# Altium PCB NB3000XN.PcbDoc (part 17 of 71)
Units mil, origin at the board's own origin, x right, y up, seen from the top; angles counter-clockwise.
Board outline 9527.56 x 6929.77 mil, 6 copper layers (Top Layer, GND+SHIELD, MidLayer1, MidLayer2, P2 - 3V3+5V0, Bottom Layer), stack 62.375 mil thick; 832 components, 1027 nets, 4655 pads, 4981 vias.
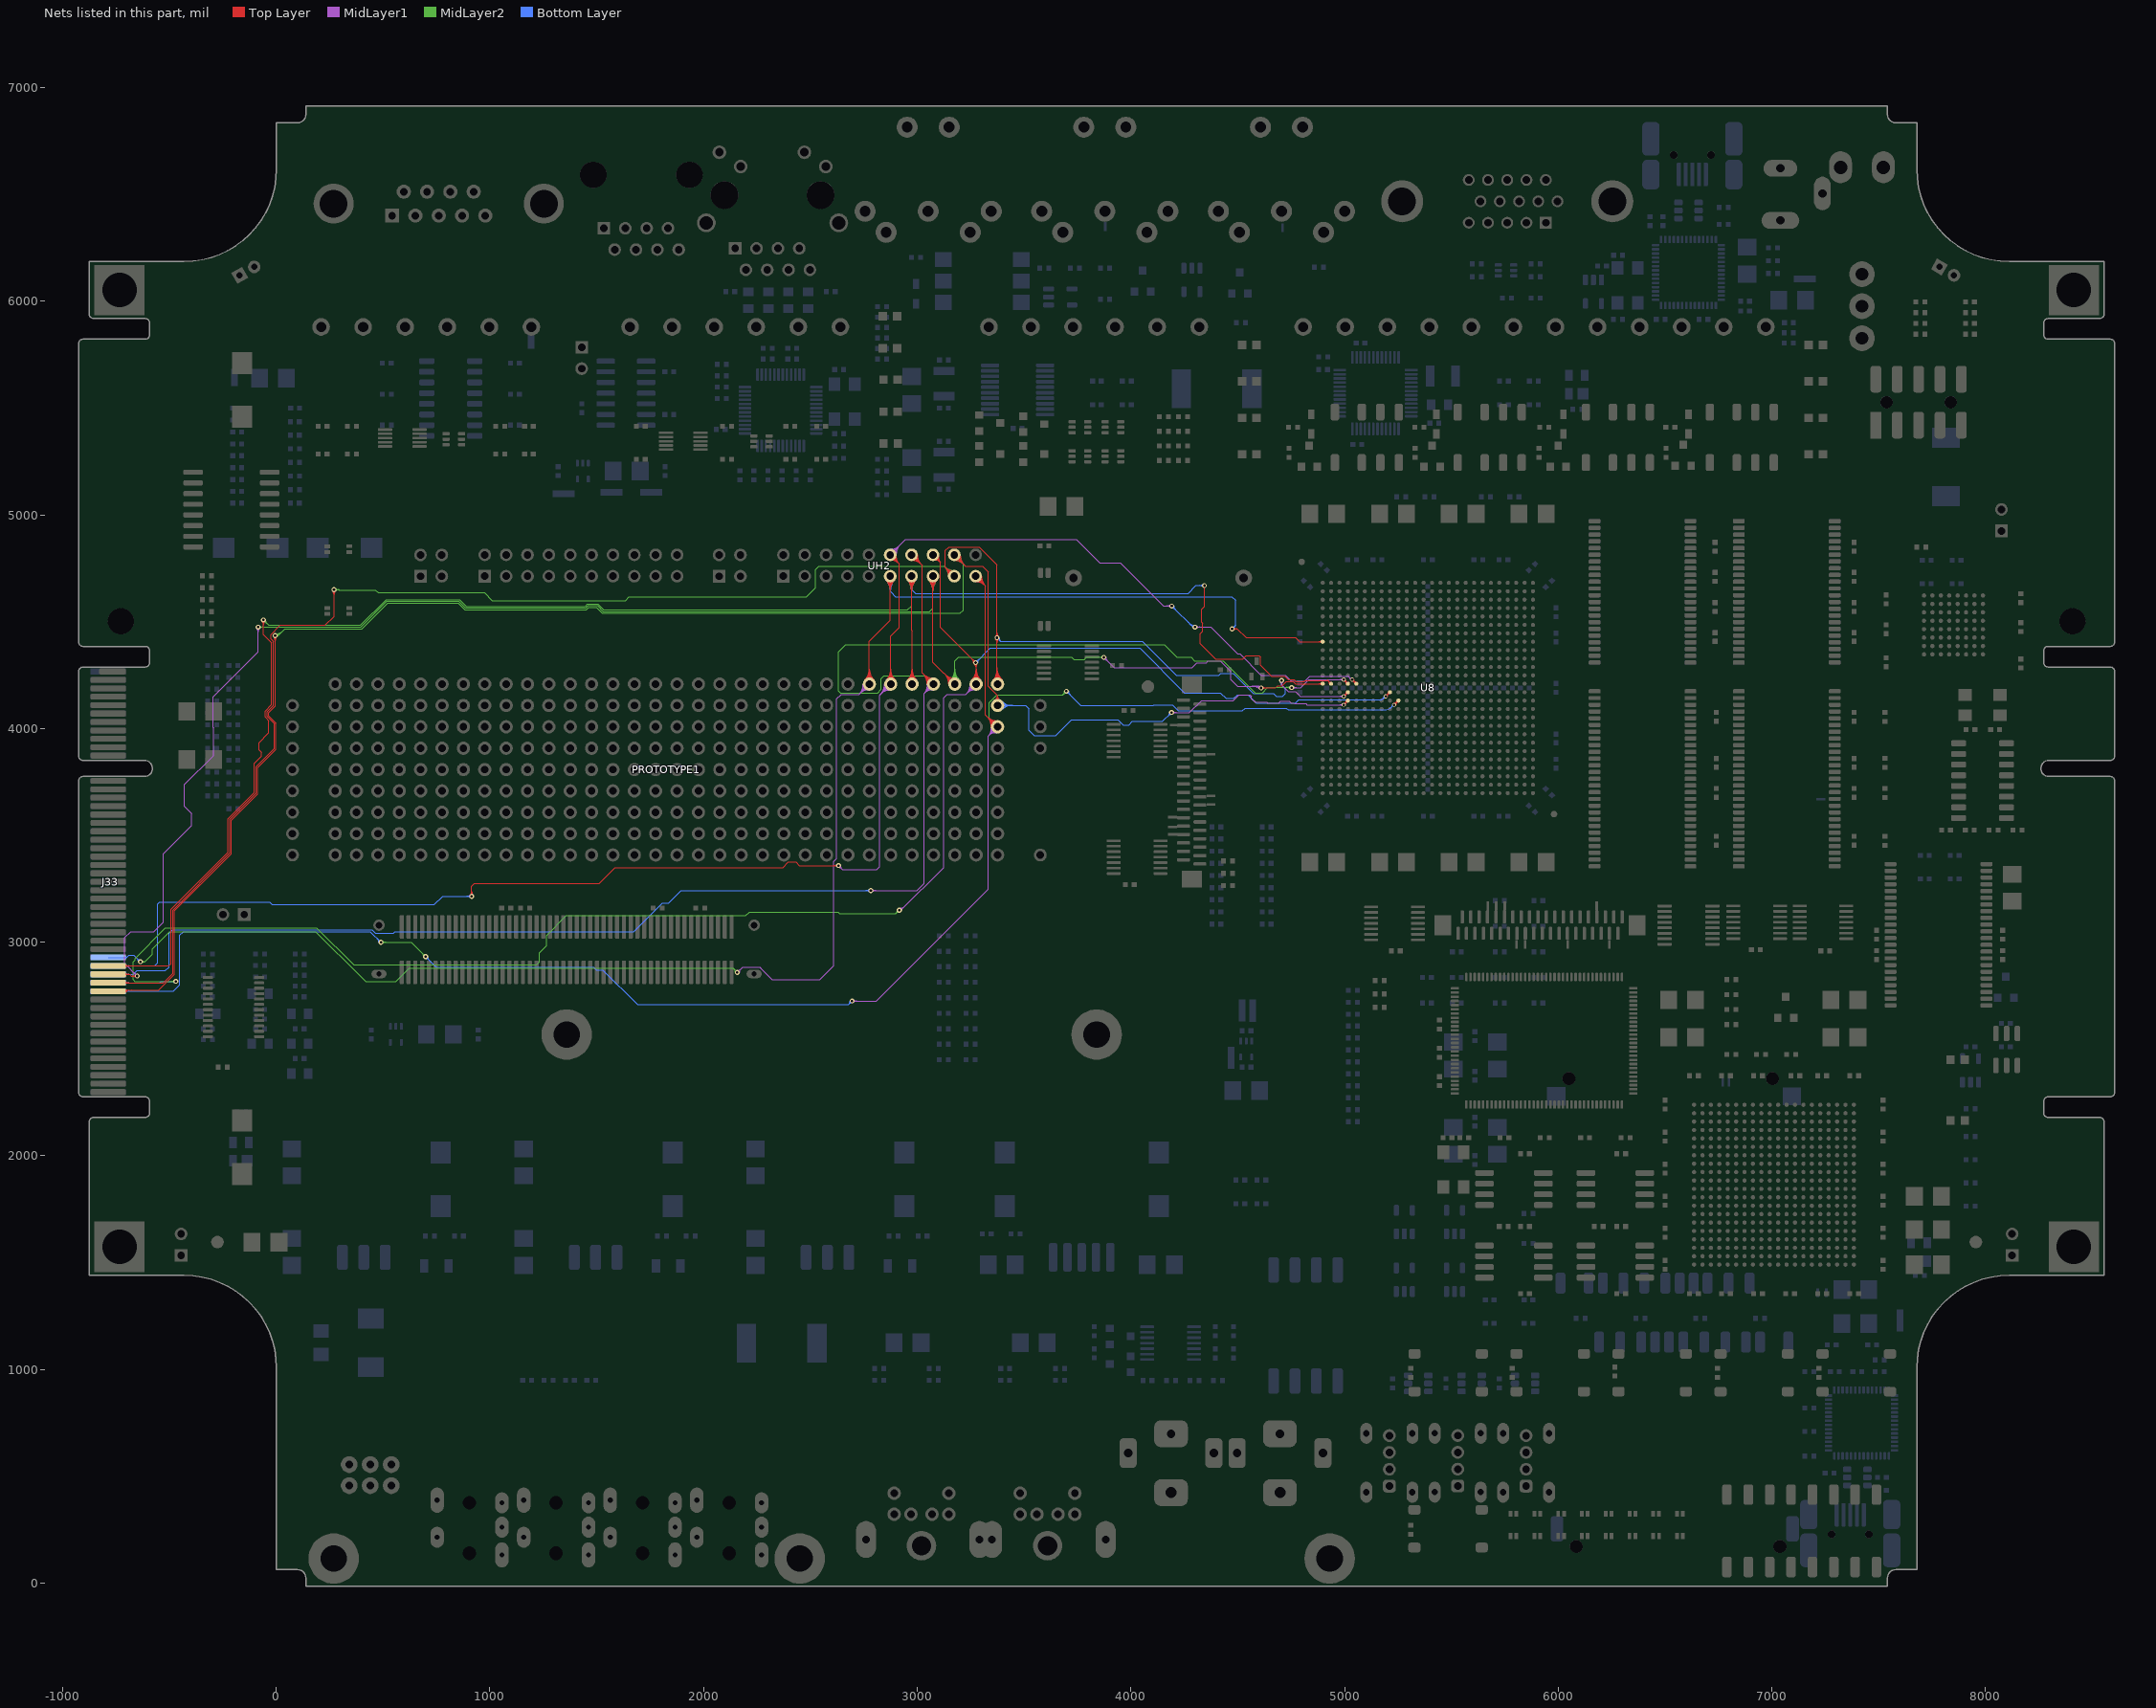
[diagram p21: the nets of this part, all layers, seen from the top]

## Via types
v1: diameter 23, hole 11.81, Top Layer to Bottom Layer, 3672 vias
v2: diameter 26, hole 11.81, Top Layer to Bottom Layer, 461 vias
v3: diameter 19, hole 11.81, Top Layer to Bottom Layer, tented both sides, 396 vias
v4: diameter 23.62, hole 11.81, Top Layer to Bottom Layer, 288 vias
v5: diameter 20, hole 11.81, Top Layer to Bottom Layer, 91 vias
v6: diameter 23, hole 11.81, Top Layer to Bottom Layer, tented both sides, 50 vias
v7: diameter 31, hole 11.81, Top Layer to Bottom Layer, 15 vias
v8: diameter 27.56, hole 11.81, Top Layer to Bottom Layer, tented both sides, 4 vias
v9: diameter 29, hole 11.81, Top Layer to Bottom Layer, 3 vias
v10: diameter 21, hole 11.81, Top Layer to Bottom Layer, 1 vias

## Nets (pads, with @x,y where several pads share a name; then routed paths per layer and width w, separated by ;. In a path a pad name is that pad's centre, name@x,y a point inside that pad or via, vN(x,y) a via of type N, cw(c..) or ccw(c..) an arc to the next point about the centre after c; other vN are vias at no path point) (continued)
ATE.UIO.IO27: J33.B33 PROTOTYPE1.H26 U8.H1 UH2.11 | length 9772.1
  Top Layer w4: PROTOTYPE1.H26@2755.62,4228.74 ccw(c2706.11,4278.25) 2776.12,4278.25 ccw(c2846.13,4278.25) PROTOTYPE1.H26@2796.63,4228.74 ; PROTOTYPE1.H26@2758.44,4225.91 ccw(c2715.77,4268.59) 2776.12,4268.59 ccw(c2836.48,4268.59) PROTOTYPE1.H26@2793.8,4225.91 ; PROTOTYPE1.H26@2761.27,4223.08 ccw(c2725.42,4258.93) 2776.12,4258.93 ccw(c2826.82,4258.93) PROTOTYPE1.H26@2790.97,4223.08 ; PROTOTYPE1.H26@2764.1,4220.26 ccw(c2735.08,4249.28) 2776.12,4249.28 ccw(c2817.16,4249.28) PROTOTYPE1.H26@2788.14,4220.26 ; PROTOTYPE1.H26@2766.93,4217.43 ccw(c2744.74,4239.62) 2776.12,4239.62 ccw(c2807.51,4239.62) PROTOTYPE1.H26@2785.31,4217.43 ; PROTOTYPE1.H26@2776.12,4208.23 2776.12,4408.37 2873.76,4506.01 UH2.11@2873.76,4713.23 ; UH2.11@2854.29,4693.77 cw(c2807.3,4646.78) 2873.76,4646.78 cw(c2940.21,4646.78) UH2.11@2893.22,4693.77 ; UH2.11@2857.12,4696.6 cw(c2816.96,4656.43) 2873.76,4656.43 cw(c2930.56,4656.43) UH2.11@2890.4,4696.6 ; UH2.11@2859.95,4699.43 cw(c2826.61,4666.09) 2873.76,4666.09 cw(c2920.9,4666.09) UH2.11@2887.57,4699.43 ; UH2.11@2862.78,4702.25 cw(c2836.27,4675.75) 2873.76,4675.75 cw(c2911.24,4675.75) UH2.11@2884.74,4702.25 ; v1(4473.52,4466.71) 4498.29,4466.71 4539.13,4425.87 4770.7,4425.87 4790.03,4406.54 4860,4406.54 4870,4406.54 U8.H1@4897.87,4406.54 ; v1@4477.41,4462.82 cw(c4486.8,4453.43) 4486.8,4466.71 cw(c4486.8,4479.99) v1@4477.41,4470.6 ; v1@4480.24,4459.99 cw(c4496.46,4443.77) 4496.46,4466.71 cw(c4496.46,4489.64) v1@4480.24,4473.43 ; U8.H1@4892.57,4401.23 ccw(c4879.77,4388.43) 4879.77,4406.54 ccw(c4879.77,4424.64) U8.H1@4892.57,4411.84 ; U8.H1@4892.68,4401.34 ccw(c4880.15,4388.81) 4880.15,4406.54 ccw(c4880.15,4424.26) U8.H1@4892.68,4411.73
  MidLayer1 w4: v1(2157.86,2858.37) 2182.86,2883.37 2263.86,2883.37 2266.12,2881.12 ; v1@2157.86,2863.87 ccw(c2157.86,2877.15) 2167.25,2867.76 ccw(c2176.64,2858.37) v1@2163.36,2858.37 ; v1@2157.86,2867.87 ccw(c2157.86,2890.81) 2174.07,2874.59 ccw(c2190.29,2858.37) v1@2167.36,2858.37 ; 2265,2880 2320.29,2824.71 2545.21,2824.71 2610,2889.5 2610,3378.18 2623.52,3391.71 2623.52,4138.52 2645,4160 2727.89,4160 ; PROTOTYPE1.H26@2747.13,4207.7 cw(c2681.42,4206.47) 2727.89,4160 ; PROTOTYPE1.H26@2751.13,4207.77 cw(c2694.48,4206.72) 2734.54,4166.66 cw(c2774.6,4126.59) PROTOTYPE1.H26@2775.66,4183.24 ; PROTOTYPE1.H26@2755.12,4207.84 cw(c2707.54,4206.96) 2741.19,4173.31 cw(c2774.85,4139.66) PROTOTYPE1.H26@2775.73,4187.24 ; PROTOTYPE1.H26@2759.12,4207.92 cw(c2720.61,4207.2) 2747.85,4179.96 cw(c2775.09,4152.72) PROTOTYPE1.H26@2775.8,4191.24 ; PROTOTYPE1.H26@2775.58,4179.24 ccw(c2774.36,4113.53) 2727.89,4160 ; PROTOTYPE1.H26@2776.12,4208.23 2727.89,4160
  MidLayer2 w4: v1(-635.48,2908.37) -615,2908.37 ; v1@-631.28,2904.82 cw(c-623.62,2898.35) -623.62,2908.37 cw(c-623.62,2918.4) v1@-631.28,2911.93 ; v1@-628.22,2902.24 cw(c-615,2891.06) -615,2908.37 ; v1@-628.22,2914.51 ccw(c-615,2925.69) -615,2908.37 ; v1@2148.36,2858.37 ccw(c2125.42,2858.37) 2141.64,2874.59 ccw(c2157.86,2890.81) v1@2157.86,2867.87 ; v1@2152.36,2858.37 ccw(c2139.08,2858.37) 2148.47,2867.76 ccw(c2157.86,2877.15) v1@2157.86,2863.87 ; v1(2157.86,2858.37) 2138.23,2878 623,2878 560,2815 418.69,2815 395.84,2837.85 183.65,3050.04 -498.5,3050.04 -580,2968.54 -580,2943.37 -615,2908.37
  Bottom Layer w4: J33.B33@-785.98,2928.45 -701.3,2928.45 ; J33.B33@-705.79,2925.1 cw(c-701.31,2923.77) -701.31,2928.45 ; J33.B33@-705.79,2931.8 ccw(c-701.31,2933.13) -701.31,2928.45 ; v1@-644.98,2908.37 ccw(c-667.91,2908.37) -651.69,2924.59 ccw(c-635.48,2940.81) v1@-635.48,2917.87 ; v1@-640.98,2908.37 ccw(c-654.25,2908.37) -644.86,2917.76 ccw(c-635.48,2927.15) v1@-635.48,2913.87 ; v1(-635.48,2908.37) -667.45,2940.35 -689.41,2940.35 -701.3,2928.45 ; UH2.11@2854.29,4693.77 cw(c2804.3,4643.78) 2875,4643.78 ; UH2.11@2857.12,4696.6 cw(c2813.96,4653.44) 2875,4653.44 ; UH2.11@2859.95,4699.43 cw(c2823.62,4663.09) 2875,4663.09 ; UH2.11@2862.78,4702.25 cw(c2833.28,4672.75) 2875,4672.75 ; UH2.11@2865.61,4705.08 cw(c2842.93,4682.41) 2875,4682.41 ; UH2.11@2873.76,4713.23 UH2.11@2875,4713.23 ; 2875,4649.77 cw(c2937.22,4649.77) UH2.11@2893.22,4693.77 ; 2875,4659.43 cw(c2927.56,4659.43) UH2.11@2890.4,4696.6 ; 2875,4669.09 cw(c2917.91,4669.09) UH2.11@2887.57,4699.43 ; 2875,4678.74 cw(c2908.25,4678.74) UH2.11@2884.74,4702.25 ; UH2.11@2875,4715 UH2.11@2875,4713.23 ; v1(4473.52,4466.71) 4490.19,4483.37 4490.19,4600.04 4473.52,4616.71 2898.52,4616.71 2875,4640.23 UH2.11@2875,4713.23 ; v1@4473.52,4472.21 ccw(c4473.52,4485.49) 4482.91,4476.1 ccw(c4492.3,4466.71) v1@4479.02,4466.71 ; v1@4473.52,4476.21 ccw(c4473.52,4499.14) 4489.74,4482.93 ccw(c4505.96,4466.71) v1@4483.02,4466.71
ATE.UIO.IO28: J33.B34 PROTOTYPE1.H27 U8.N5 UH2.12 | length 10153.7
  Top Layer w4: v1@908.3,3221.74 ccw(c892.14,3238.01) 915.07,3237.93 ccw(c938.01,3237.86) v1@921.74,3221.7 ; v1@911.12,3218.9 ccw(c901.76,3228.32) 915.04,3228.28 ccw(c928.32,3228.24) v1@918.9,3218.88 ; v1(915,3215) 915.15,3262.19 928,3275.04 1512.21,3275.04 1586.88,3349.71 2371.52,3349.71 2396.86,3375.04 2431.86,3375.04 2448.52,3358.37 v1(2631.86,3358.37) ; v1@2625.14,3351.66 ccw(c2608.92,3335.44) 2608.92,3358.37 ccw(c2608.92,3381.31) v1@2625.14,3365.09 ; v1@2627.97,3354.49 ccw(c2618.58,3345.1) 2618.58,3358.37 ccw(c2618.58,3371.65) v1@2627.97,3362.26 ; PROTOTYPE1.H27@2855.62,4228.74 ccw(c2806.11,4278.25) 2876.12,4278.25 ccw(c2946.13,4278.25) PROTOTYPE1.H27@2896.63,4228.74 ; PROTOTYPE1.H27@2858.44,4225.91 ccw(c2815.77,4268.59) 2876.12,4268.59 ccw(c2936.48,4268.59) PROTOTYPE1.H27@2893.8,4225.91 ; PROTOTYPE1.H27@2861.27,4223.08 ccw(c2825.42,4258.93) 2876.12,4258.93 ccw(c2926.82,4258.93) PROTOTYPE1.H27@2890.97,4223.08 ; PROTOTYPE1.H27@2864.1,4220.26 ccw(c2835.08,4249.28) 2876.12,4249.28 ccw(c2917.16,4249.28) PROTOTYPE1.H27@2888.14,4220.26 ; PROTOTYPE1.H27@2866.93,4217.43 ccw(c2844.74,4239.62) 2876.12,4239.62 ccw(c2907.51,4239.62) PROTOTYPE1.H27@2885.31,4217.43 ; UH2.12@2873.76,4813.23 2915.19,4771.8 ; UH2.12@2875.2,4797.77 cw(c2877.75,4770.48) 2897.13,4789.86 cw(c2916.51,4809.24) UH2.12@2889.22,4811.79 ; UH2.12@2875.57,4793.79 cw(c2878.77,4759.47) 2903.15,4783.84 cw(c2927.52,4808.22) UH2.12@2893.2,4811.42 ; UH2.12@2875.94,4789.81 cw(c2879.8,4748.46) 2909.17,4777.82 cw(c2938.53,4807.19) UH2.12@2897.18,4811.05 ; PROTOTYPE1.H27@2876.12,4208.23 2876.12,4433.37 2915.19,4472.44 2915.19,4771.8 ; UH2.12@2876.32,4785.83 cw(c2880.83,4737.45) 2915.19,4771.8 ; UH2.12@2901.17,4810.68 ccw(c2949.55,4806.16) 2915.19,4771.8 ; v3(5035.67,4229.37) U8.N5@5055.35,4209.69 ; U8.N5@5047.85,4209.69 ccw(c5029.75,4209.69) 5042.55,4222.49 ccw(c5055.35,4235.29) U8.N5@5055.35,4217.19 ; U8.N5@5048.01,4209.69 ccw(c5030.29,4209.69) 5042.82,4222.22 ccw(c5055.35,4234.75) U8.N5@5055.35,4217.03 ; 5048.47,4216.57 ccw(c5035.67,4203.76) 5035.67,4221.87 cw(c5035.67,4203.76) 5048.47,4216.57 ; 5048.47,4216.57 cw(c5061.28,4229.37) 5043.17,4229.37 ccw(c5061.28,4229.37) 5048.47,4216.57
  MidLayer1 w4: v1@2631.86,3348.87 cw(c2631.86,3325.94) 2648.07,3342.16 cw(c2664.29,3358.37) v1@2641.36,3358.37 ; v1@2631.86,3352.87 cw(c2631.86,3339.6) 2641.25,3348.99 cw(c2650.64,3358.37) v1@2637.36,3358.37 ; v1(2631.86,3358.37) 2650.23,3340 2810,3340 2823.52,3353.52 2823.52,4155.64 PROTOTYPE1.H27@2876.12,4208.23 ; PROTOTYPE1.H27@2847.12,4208.23 cw(c2777.11,4208.23) 2826.62,4158.73 cw(c2876.12,4109.22) PROTOTYPE1.H27@2876.12,4179.23 ; PROTOTYPE1.H27@2851.12,4208.23 cw(c2790.77,4208.23) 2833.44,4165.56 cw(c2876.12,4122.88) PROTOTYPE1.H27@2876.12,4183.23 ; PROTOTYPE1.H27@2855.12,4208.23 cw(c2804.42,4208.23) 2840.27,4172.39 cw(c2876.12,4136.54) PROTOTYPE1.H27@2876.12,4187.23 ; PROTOTYPE1.H27@2859.12,4208.23 cw(c2818.08,4208.23) 2847.1,4179.21 cw(c2876.12,4150.19) PROTOTYPE1.H27@2876.12,4191.23 ; PROTOTYPE1.H27@2863.12,4208.23 cw(c2831.74,4208.23) 2853.93,4186.04 cw(c2876.12,4163.85) PROTOTYPE1.H27@2876.12,4195.23 ; UH2.12@2873.52,4813.23 UH2.12@2873.76,4813.23 2945.54,4885 3744.71,4885 3855,4774.71 3951.61,4774.71 4152.61,4573.71 v1(4191.52,4573.71) ; UH2.12@2873.76,4828.76 ccw(c2873.76,4866.28) 2900.29,4839.75 ; UH2.12@2873.76,4832.76 ccw(c2873.76,4879.93) 2907.11,4846.58 ; UH2.12@2873.76,4836.76 ccw(c2873.76,4893.59) 2913.94,4853.41 ; UH2.12@2873.76,4840.76 ccw(c2873.76,4907.25) 2920.77,4860.23 ; UH2.12@2889.29,4813.23 cw(c2926.74,4813.23) 2900.26,4839.72 ; UH2.12@2893.29,4813.23 cw(c2940.4,4813.23) 2907.09,4846.55 ; UH2.12@2897.29,4813.23 cw(c2954.06,4813.23) 2913.91,4853.38 ; UH2.12@2901.29,4813.23 cw(c2967.71,4813.23) 2920.74,4860.21 ; v1@4184.81,4566.99 ccw(c4168.59,4550.77) 4168.59,4573.71 ccw(c4168.59,4596.64) v1@4184.81,4580.43 ; v1@4187.64,4569.82 ccw(c4178.25,4560.43) 4178.25,4573.71 ccw(c4178.25,4586.99) v1@4187.64,4577.6 ; v1@4303.89,4471.11 cw(c4313.38,4461.62) 4313.38,4475.04 ; v1@4303.89,4478.89 ccw(c4313.18,4488.18) 4313.18,4475.04 ; v1@4306.72,4468.28 cw(c4323.03,4451.97) 4323.03,4475.04 ; v1@4306.72,4481.72 ccw(c4322.84,4497.84) 4322.84,4475.04 ; 5022.09,4240.76 ccw(c5012.16,4230.83) 5012.16,4244.88 4918.62,4244.88 4870,4244.88 4860,4244.88 4837.69,4244.88 4815.19,4222.37 4751.19,4222.37 4723.52,4250.04 4609.84,4250.04 4509.84,4350.04 4498.52,4350.04 4373.52,4475.04 v1@4300.04,4475.04 ; v3@5028.2,4228.72 ccw(c5010.16,4227.14) 5021.8,4241.01 ccw(c5033.44,4254.88) v3@5035.02,4236.84 ; v1(4300,4475) v1@4300.04,4475.04
  Bottom Layer w4: J33.B34@-785.98,2889.08 -567.81,2889.08 -554.41,2902.48 -554.41,3179.28 -546.69,3187 -29.82,3187 -19,3176.19 740.09,3176.19 778.9,3215 v1(915,3215) ; J33.B34@-711.58,2883.58 cw(c-698.3,2870.3) -698.3,2889.08 ; J33.B34@-711.58,2894.58 ccw(c-698.3,2907.86) -698.3,2889.08 ; J33.B34@-708.76,2880.75 cw(c-688.65,2860.64) -688.65,2889.08 cw(c-688.64,2917.52) J33.B34@-708.76,2897.41 ; v1@908.28,3208.28 ccw(c892.06,3192.06) 892.06,3215 ccw(c892.06,3237.93) v1@908.28,3221.72 ; v1@911.11,3211.11 ccw(c901.72,3201.72) 901.72,3215 ccw(c901.72,3228.28) v1@911.11,3218.89 ; v1@4191.52,4564.21 cw(c4191.52,4541.27) 4207.74,4557.49 cw(c4223.96,4573.71) v1@4201.02,4573.71 ; v1@4191.52,4568.21 cw(c4191.52,4554.93) 4200.91,4564.32 cw(c4210.3,4573.71) v1@4197.02,4573.71 ; v1(4191.52,4573.71) 4290.19,4475.04 4306.86,4475.04 4306.82,4475 v1(4300,4475) ; 4267.11,4498.13 ccw(c4300,4531.02) v1@4300,4484.5 ; 4273.93,4491.3 ccw(c4300,4517.36) v1@4300,4480.5 ; 4280.76,4484.47 ccw(c4300,4503.71) v1@4300,4476.5 ; 4287.59,4477.64 ccw(c4300,4490.05) v1@4300,4472.5
ATE.UIO.IO29: J33.A34 PROTOTYPE1.H28 U8.N2 UH2.13 | length 9997.1
  Top Layer w4: J33.A34@-785.98,2889.08 -503.06,2889.08 -492.14,2900 -492.14,3154.02 -292.32,3353.85 -225.35,3420.81 -225.35,3578.34 -102,3701.69 -102,3838.1 -68.14,3871.96 -68.14,3888.14 -81,3901 -81,3933.85 -35,3979.85 -35,4037.56 -51.48,4054.04 -51.48,4081.15 -21,4111.63 -21,4401 -59.81,4439.81 v1(-59.81,4508.37) ; J33.A34@-711.58,2883.58 cw(c-698.3,2870.3) -698.3,2889.08 ; J33.A34@-711.58,2894.58 ccw(c-698.3,2907.86) -698.3,2889.08 ; J33.A34@-708.76,2880.75 cw(c-688.65,2860.64) -688.65,2889.08 cw(c-688.64,2917.52) J33.A34@-708.76,2897.41 ; v1@-66.53,4501.66 cw(c-82.74,4485.44) -59.81,4485.44 cw(c-36.87,4485.44) v1@-53.09,4501.66 ; v1@-63.7,4504.49 cw(c-73.09,4495.1) -59.81,4495.1 cw(c-46.53,4495.1) v1@-55.92,4504.49 ; UH2.13@2954.29,4693.77 cw(c2907.3,4646.78) 2973.76,4646.78 cw(c3040.21,4646.78) UH2.13@2993.22,4693.77 ; PROTOTYPE1.H28@2955.62,4228.74 ccw(c2906.11,4278.25) 2976.12,4278.25 ccw(c3046.13,4278.25) PROTOTYPE1.H28@2996.63,4228.74 ; UH2.13@2957.12,4696.6 cw(c2916.96,4656.43) 2973.76,4656.43 cw(c3030.56,4656.43) UH2.13@2990.4,4696.6 ; PROTOTYPE1.H28@2958.44,4225.91 ccw(c2915.77,4268.59) 2976.12,4268.59 ccw(c3036.48,4268.59) PROTOTYPE1.H28@2993.8,4225.91 ; UH2.13@2959.95,4699.43 cw(c2926.61,4666.09) 2973.76,4666.09 cw(c3020.9,4666.09) UH2.13@2987.57,4699.43 ; PROTOTYPE1.H28@2961.27,4223.08 ccw(c2925.42,4258.93) 2976.12,4258.93 ccw(c3026.82,4258.93) PROTOTYPE1.H28@2990.97,4223.08 ; UH2.13@2962.78,4702.25 cw(c2936.27,4675.75) 2973.76,4675.75 cw(c3011.24,4675.75) UH2.13@2984.74,4702.25 ; PROTOTYPE1.H28@2964.1,4220.26 ccw(c2935.08,4249.28) 2976.12,4249.28 ccw(c3017.16,4249.28) PROTOTYPE1.H28@2988.14,4220.26 ; PROTOTYPE1.H28@2966.93,4217.43 ccw(c2944.74,4239.62) 2976.12,4239.62 ccw(c3007.51,4239.62) PROTOTYPE1.H28@2985.31,4217.43 ; UH2.13@2973.76,4713.23 2973.76,4460.74 2976.12,4458.37 PROTOTYPE1.H28@2976.12,4208.23 ; v1(4344.52,4669.37) 4344.52,4570.84 4332,4558.31 4332,4497.27 4335,4494.27 4335,4454.52 4331.86,4451.37 ; U8.N2@4929.9,4209.69 ccw(c4912.17,4209.69) 4924.71,4222.22 ; U8.N2@4937.24,4217.03 cw(c4937.24,4234.75) 4924.71,4222.22 ; 4324.02,4443.54 4331.86,4451.37 ; 4324.02,4443.54 4331.86,4451.37 ; 4324.02,4443.54 4324.02,4397.81 4396.8,4325.04 4523.52,4325.04 4540.19,4341.71 4600.52,4341.71 4606.86,4335.37 4606.86,4296.71 4658.52,4245.04 4720.21,4245.04 4736.54,4228.71 4746,4228.71 4762.92,4228.71 4771.63,4220 4786.9,4220 4801,4220 4810,4220 4815.19,4225.19 4855.26,4225.19 4860,4225.19 4870,4225.19 4917.53,4225.19 cw(c4917.53,4215.04) 4924.71,4222.22
  MidLayer2 w4: v1@-59.81,4498.87 cw(c-59.81,4475.94) -43.59,4492.16 cw(c-27.37,4508.37) v1@-50.31,4508.37 ; v1@-59.81,4502.87 cw(c-59.81,4489.6) -50.42,4498.99 cw(c-41.03,4508.37) v1@-54.31,4508.37 ; v1(-59.81,4508.37) -34.81,4483.37 394.96,4483.37 515.4,4603.81 858,4603.81 889.31,4572.5 1445.98,4572.5 1448.52,4575.04 1456.86,4583.37 1505.5,4583.37 1532.88,4556 2955,4556 2973.76,4574.76 UH2.13@2973.76,4713.23 ; UH2.13@2954.29,4693.77 cw(c2907.3,4646.78) 2973.76,4646.78 cw(c3040.22,4646.78) UH2.13@2993.22,4693.77 ; UH2.13@2957.12,4696.6 cw(c2916.96,4656.43) 2973.76,4656.43 cw(c3030.56,4656.43) UH2.13@2990.4,4696.6 ; UH2.13@2959.95,4699.43 cw(c2926.62,4666.09) 2973.76,4666.09 cw(c3020.9,4666.09) UH2.13@2987.57,4699.43 ; UH2.13@2962.78,4702.25 cw(c2936.27,4675.75) 2973.76,4675.75 cw(c3011.25,4675.75) UH2.13@2984.74,4702.25
  Bottom Layer w4: UH2.13@2955.3,4692.81 cw(c2917.73,4651.24) 2973.76,4651.24 ; UH2.13@2957.98,4695.78 cw(c2925.87,4660.25) 2973.76,4660.25 cw(c3021.65,4660.25) UH2.13@2989.54,4695.78 ; UH2.13@2960.66,4698.75 cw(c2934.01,4669.26) 2973.76,4669.26 cw(c3013.51,4669.26) UH2.13@2986.85,4698.75 ; UH2.13@2963.35,4701.72 cw(c2942.15,4678.27) 2973.76,4678.27 cw(c3005.37,4678.27) UH2.13@2984.17,4701.72 ; UH2.13@2973.76,4713.23 2973.76,4651.24 ; UH2.13@2992.22,4692.81 ccw(c3029.79,4651.24) 2973.76,4651.24 ; v1@4337.81,4662.66 ccw(c4321.59,4646.44) 4321.59,4669.37 ccw(c4321.59,4692.31) v1@4337.81,4676.09 ; v1@4340.64,4665.49 ccw(c4331.25,4656.1) 4331.25,4669.37 ccw(c4331.25,4682.65) v1@4340.64,4673.26 ; v1(4344.52,4669.37) 4304.37,4669.37 4267.71,4632.71 2992.29,4632.71 2973.76,4651.24
ATE.UIO.IO30: J33.B35 PROTOTYPE1.H29 U8.N4 UH2.14 | length 10675.6
  Top Layer w4: UH2.14@2973.76,4785.71 cw(c2973.76,4719.25) 3020.75,4766.24 cw(c3067.74,4813.23) UH2.14@3001.29,4813.23 ; UH2.14@2973.76,4789.71 cw(c2973.76,4732.91) 3013.92,4773.07 cw(c3054.09,4813.23) UH2.14@2997.29,4813.23 ; UH2.14@2973.76,4793.71 cw(c2973.76,4746.56) 3007.09,4779.9 cw(c3040.43,4813.23) UH2.14@2993.29,4813.23 ; UH2.14@2973.76,4797.71 cw(c2973.76,4760.22) 3000.27,4786.73 cw(c3026.77,4813.23) UH2.14@2989.29,4813.23 ; UH2.14@2973.76,4813.23 3023.52,4763.47 3023.52,4260.83 PROTOTYPE1.H29@3076.12,4208.23 ; PROTOTYPE1.H29@3047.12,4208.23 ccw(c2977.11,4208.23) 3026.62,4257.74 ccw(c3076.12,4307.25) PROTOTYPE1.H29@3076.12,4237.23 ; PROTOTYPE1.H29@3051.12,4208.23 ccw(c2990.77,4208.23) 3033.44,4250.91 ccw(c3076.12,4293.59) PROTOTYPE1.H29@3076.12,4233.23 ; PROTOTYPE1.H29@3055.12,4208.23 ccw(c3004.42,4208.23) 3040.27,4244.08 ccw(c3076.12,4279.93) PROTOTYPE1.H29@3076.12,4229.23 ; PROTOTYPE1.H29@3059.12,4208.23 ccw(c3018.08,4208.23) 3047.1,4237.26 ccw(c3076.12,4266.28) PROTOTYPE1.H29@3076.12,4225.23 ; PROTOTYPE1.H29@3063.12,4208.23 ccw(c3031.74,4208.23) 3053.93,4230.43 ccw(c3076.12,4252.62) PROTOTYPE1.H29@3076.12,4221.23 ; v3(4996.3,4229.37) U8.N4@5015.98,4209.69 ; U8.N4@5008.48,4209.69 ccw(c4990.38,4209.69) 5003.18,4222.49 ccw(c5015.98,4235.29) U8.N4@5015.98,4217.19 ; U8.N4@5008.64,4209.69 ccw(c4990.92,4209.69) 5003.45,4222.22 ccw(c5015.98,4234.75) U8.N4@5015.98,4217.03 ; 5009.1,4216.57 cw(c5021.91,4229.37) 5003.8,4229.37 ccw(c5021.91,4229.37) 5009.1,4216.57 ; 5009.1,4216.57 ccw(c4996.3,4203.76) 4996.3,4221.87 cw(c4996.3,4203.76) 5009.1,4216.57
  MidLayer1 w4: v1(2782.86,3241.71) 2998.52,3241.71 3031.86,3275.04 3031.86,4163.97 ; v1@2786.75,3237.82 cw(c2796.14,3228.43) 2796.14,3241.71 cw(c2796.14,3254.99) v1@2786.75,3245.6 ; v1@2789.57,3234.99 cw(c2805.79,3218.77) 2805.79,3241.71 cw(c2805.79,3264.64) v1@2789.57,3248.43 ; PROTOTYPE1.H29@3047.22,4205.85 cw(c2994.34,4201.49) 3031.86,4163.97 ; PROTOTYPE1.H29@3051.21,4206.18 cw(c3005.62,4202.42) 3037.96,4170.08 cw(c3070.31,4137.74) PROTOTYPE1.H29@3074.07,4183.32 ; PROTOTYPE1.H29@3055.19,4206.51 cw(c3016.9,4203.35) 3044.07,4176.18 cw(c3071.24,4149.02) PROTOTYPE1.H29@3074.39,4187.31 ; PROTOTYPE1.H29@3059.18,4206.84 cw(c3028.18,4204.28) 3050.17,4182.29 cw(c3072.17,4160.3) PROTOTYPE1.H29@3074.72,4191.29 ; PROTOTYPE1.H29@3073.74,4179.33 ccw(c3069.37,4126.46) 3031.86,4163.97 ; PROTOTYPE1.H29@3076.12,4208.23 3031.86,4163.97 ; v1(4752.52,4191.71) 4795.84,4191.71 4833.5,4229.37 4855.26,4229.37 4860,4229.37 4870,4229.37 4918.62,4229.37 v3(4996.3,4229.37) ; v1@4756.41,4187.82 cw(c4765.8,4178.43) 4765.8,4191.71 cw(c4765.8,4204.99) v1@4756.41,4195.6 ; v1@4759.24,4184.99 cw(c4775.46,4168.77) 4775.46,4191.71 cw(c4775.46,4214.64) v1@4759.24,4198.43 ; v3@4991.11,4224.18 ccw(c4978.57,4211.64) 4978.57,4229.37 ccw(c4978.57,4247.1) v3@4991.11,4234.56 ; 4978.19,4229.37 cw(c4978.19,4211.26) 4991,4224.07 ccw(c4978.19,4211.26) 4978.19,4229.37 ; 4978.19,4229.37 ccw(c4978.19,4247.48) 4991,4234.67 cw(c4978.19,4247.48) 4978.19,4229.37
  MidLayer2 w4: PROTOTYPE1.H29@3047.62,4213.59 ccw(c3010.68,4220.52) 3037.26,4247.1 ; PROTOTYPE1.H29@3051.55,4212.85 ccw(c3019.7,4218.83) 3042.62,4241.74 ccw(c3065.53,4264.65) PROTOTYPE1.H29@3071.51,4232.81 ; PROTOTYPE1.H29@3055.48,4212.11 ccw(c3028.73,4217.13) 3047.98,4236.38 ccw(c3067.22,4255.63) PROTOTYPE1.H29@3072.25,4228.87 ; PROTOTYPE1.H29@3059.41,4211.37 ccw(c3037.76,4215.44) 3053.34,4231.02 ccw(c3068.92,4246.6) PROTOTYPE1.H29@3072.98,4224.94 ; PROTOTYPE1.H29@3070.77,4236.74 cw(c3063.83,4273.68) 3037.26,4247.1 ; PROTOTYPE1.H29@3076.12,4208.23 3037.25,4247.1 ; 4727.17,4192.71 cw(c4727.17,4166.36) v1@4745.81,4184.99 ; 4732,4192.71 ccw(c4732,4212.23) v1@4745.81,4198.43 ; 4736.83,4192.71 cw(c4736.83,4176.02) v1@4748.64,4187.82 ; v1(4752.52,4191.71) 4751.52,4192.71 4641.19,4192.71 4615.19,4166.71 4581.86,4166.71 4432.52,4316.04 4298.86,4316.04 4281.52,4333.37 4215.19,4333.37 4156.86,4391.71 2665.19,4391.71 2631.86,4358.37 2631.86,4175.04 2640.19,4166.71 2815.19,4166.71 2831.86,4183.37 2831.86,4233.37 2845.59,4247.1 3037.25,4247.1
  Bottom Layer w4: J33.B35@-785.98,2849.71 -668.14,2849.71 -651.14,2866.71 -518.14,2866.71 -501.48,2883.37 -501.48,3041.71 -484.81,3058.37 448.33,3058.37 465,3041.71 550,3041.71 556.6,3048.31 1672.48,3048.31 1807.21,3183.04 1836.88,3183.04 1895.54,3241.71 v1(2782.86,3241.71) ; J33.B35@-711.58,2844.21 cw(c-698.3,2830.93) -698.3,2849.71 ; J33.B35@-711.58,2855.21 ccw(c-698.3,2868.49) -698.3,2849.71 ; J33.B35@-708.76,2841.38 cw(c-688.65,2821.27) -688.65,2849.71 cw(c-688.64,2878.15) J33.B35@-708.76,2858.04 ; v1@2776.14,3234.99 ccw(c2759.92,3218.77) 2759.92,3241.71 ccw(c2759.92,3264.64) v1@2776.14,3248.43 ; v1@2778.97,3237.82 ccw(c2769.58,3228.43) 2769.58,3241.71 ccw(c2769.58,3254.99) v1@2778.97,3245.6
ATE.UIO.IO31: J33.A35 PROTOTYPE1.H30 U8.N1 UH2.15 | length 10161.6
  Top Layer w4: J33.A35@-785.98,2849.71 -685,2849.71 -677,2841.71 v1(-650.48,2841.71) ; J33.A35@-711.58,2844.21 cw(c-698.3,2830.93) -698.3,2849.71 ; J33.A35@-711.58,2855.21 ccw(c-698.3,2868.49) -698.3,2849.71 ; J33.A35@-708.76,2841.38 cw(c-688.65,2821.27) -688.65,2849.71 cw(c-688.64,2878.15) J33.A35@-708.76,2858.04 ; v1@-657.19,2834.99 ccw(c-673.41,2818.77) -673.41,2841.71 ccw(c-673.41,2864.64) v1@-657.19,2848.43 ; v1@-654.36,2837.82 ccw(c-663.75,2828.43) -663.75,2841.71 ccw(c-663.75,2854.99) v1@-654.36,2845.6 ; UH2.15@3054.29,4693.77 cw(c3007.3,4646.78) 3073.76,4646.78 cw(c3140.21,4646.78) UH2.15@3093.22,4693.77 ; UH2.15@3057.12,4696.6 cw(c3016.96,4656.43) 3073.76,4656.43 cw(c3130.56,4656.43) UH2.15@3090.4,4696.6 ; UH2.15@3059.95,4699.43 cw(c3026.61,4666.09) 3073.76,4666.09 cw(c3120.9,4666.09) UH2.15@3087.57,4699.43 ; UH2.15@3062.78,4702.25 cw(c3036.27,4675.75) 3073.76,4675.75 cw(c3111.24,4675.75) UH2.15@3084.74,4702.25 ; UH2.15@3073.76,4713.23 3073.76,4310.6 PROTOTYPE1.H30@3176.12,4208.23 ; PROTOTYPE1.H30@3147.12,4208.23 ccw(c3077.11,4208.23) 3126.62,4257.74 ccw(c3176.12,4307.25) PROTOTYPE1.H30@3176.12,4237.23 ; PROTOTYPE1.H30@3151.12,4208.23 ccw(c3090.77,4208.23) 3133.44,4250.91 ccw(c3176.12,4293.59) PROTOTYPE1.H30@3176.12,4233.23 ; PROTOTYPE1.H30@3155.12,4208.23 ccw(c3104.42,4208.23) 3140.27,4244.08 ccw(c3176.12,4279.93) PROTOTYPE1.H30@3176.12,4229.23 ; PROTOTYPE1.H30@3159.12,4208.23 ccw(c3118.08,4208.23) 3147.1,4237.26 ccw(c3176.12,4266.28) PROTOTYPE1.H30@3176.12,4225.23 ; PROTOTYPE1.H30@3163.12,4208.23 ccw(c3131.74,4208.23) 3153.93,4230.43 ccw(c3176.12,4252.62) PROTOTYPE1.H30@3176.12,4221.23 ; v1(4610,4190) 4677.17,4190 4687.88,4200.71 4707.52,4200.71 4727.52,4220.71 4759.61,4220.71 4770.63,4209.69 4813,4209.69 ; v1@4613.89,4186.11 cw(c4623.28,4176.72) 4623.28,4190 cw(c4623.28,4203.28) v1@4613.89,4193.89 ; v1@4616.72,4183.28 cw(c4632.93,4167.06) 4632.93,4190 cw(c4632.93,4212.93) v1@4616.72,4196.72 ; 4811.31,4209.69 4813,4209.69 ; 4855.26,4209.68 4856.86,4209.68 ; U8.N1@4892.57,4204.38 ccw(c4879.77,4191.58) 4879.77,4209.69 ccw(c4879.77,4227.79) U8.N1@4892.57,4214.99 ; U8.N1@4892.68,4204.49 ccw(c4880.15,4191.96) 4880.15,4209.69 ccw(c4880.15,4227.41) U8.N1@4892.68,4214.88 ; U8.N1@4897.87,4209.69 4870,4209.69 4860,4209.69 4825,4209.69 4813,4209.69
  MidLayer1 w4: v1@-659.98,2841.71 ccw(c-682.91,2841.71) -666.69,2857.93 ccw(c-650.48,2874.14) v1@-650.48,2851.21 ; v1@-655.98,2841.71 ccw(c-669.25,2841.71) -659.86,2851.1 ccw(c-650.48,2860.49) v1@-650.48,2847.21 ; v1(-650.48,2841.71) -709.81,2901.04 -709.81,3021.46 -681.22,3050.04 -572.33,3050.04 -529,3093.37 -529,3201.2 ; -528.98,3201.22 -528.98,3412.99 -395,3546.97 -395,3602.38 -428.81,3636.19 -428.81,3737.82 -293.23,3873.4 -293.23,4003.46 -295,4005.23 -295,4148.18 -84.81,4358.37 v1(-84.81,4475.04) ; v1@-91.53,4468.32 cw(c-107.74,4452.11) -84.81,4452.11 cw(c-61.87,4452.11) v1@-78.09,4468.32 ; v1@-88.7,4471.15 cw(c-98.09,4461.76) -84.81,4461.76 cw(c-71.53,4461.76) v1@-80.92,4471.15 ; v1@3873.52,4323.87 cw(c3873.52,4300.94) 3889.74,4317.16 cw(c3905.96,4333.37) v1@3883.02,4333.37 ; v1@3873.52,4327.87 cw(c3873.52,4314.6) 3882.91,4323.99 cw(c3892.3,4333.37) v1@3879.02,4333.37 ; v1(3873.52,4333.37) 3921.9,4285 4286.79,4285 4310,4308.21 4353.21,4308.21 4361.54,4316.54 4419.66,4316.54 4468.86,4267.35 4468.86,4229.71 4499.86,4198.71 4601.29,4198.71 v1(4610,4190) ; 4566.04,4198.71 cw(c4566.04,4146.04) v1@4603.28,4183.28 ; 4575.7,4198.71 cw(c4575.7,4155.7) v1@4606.11,4186.11 ; 4585.36,4198.71 cw(c4585.36,4165.36) v1@4608.94,4188.94 ; 4595.01,4198.71 cw(c4595.01,4175.01) v1@4611.77,4191.77
  MidLayer2 w4: v1(-84.81,4475.04) 397.94,4475.04 518.71,4595.81 854.19,4595.81 885.5,4564.5 1449.3,4564.5 1460.17,4575.37 1502.19,4575.37 1529.56,4548 3058,4548 3073.76,4563.76 UH2.15@3073.76,4713.23 ; v1@-80.92,4471.15 cw(c-71.53,4461.76) -71.53,4475.04 cw(c-71.53,4488.32) v1@-80.92,4478.93 ; v1@-78.09,4468.32 cw(c-61.87,4452.11) -61.87,4475.04 cw(c-61.87,4497.98) v1@-78.09,4481.76 ; UH2.15@3054.29,4693.77 cw(c3007.3,4646.78) 3073.76,4646.78 cw(c3140.22,4646.78) UH2.15@3093.22,4693.77 ; UH2.15@3057.12,4696.6 cw(c3016.96,4656.43) 3073.76,4656.43 cw(c3130.56,4656.43) UH2.15@3090.4,4696.6 ; UH2.15@3059.95,4699.43 cw(c3026.62,4666.09) 3073.76,4666.09 cw(c3120.9,4666.09) UH2.15@3087.57,4699.43 ; UH2.15@3062.78,4702.25 cw(c3036.27,4675.75) 3073.76,4675.75 cw(c3111.25,4675.75) UH2.15@3084.74,4702.25 ; PROTOTYPE1.H30@3155.62,4228.74 ccw(c3106.1,4278.25) 3176.12,4278.25 ; PROTOTYPE1.H30@3158.44,4225.91 ccw(c3115.76,4268.6) 3176.12,4268.6 ccw(c3236.47,4268.58) PROTOTYPE1.H30@3193.8,4225.91 ; PROTOTYPE1.H30@3161.27,4223.08 ccw(c3125.42,4258.94) 3176.12,4258.94 ccw(c3226.81,4258.93) PROTOTYPE1.H30@3190.97,4223.08 ; PROTOTYPE1.H30@3164.1,4220.26 ccw(c3135.07,4249.28) 3176.12,4249.28 ccw(c3217.16,4249.27) PROTOTYPE1.H30@3188.14,4220.26 ; PROTOTYPE1.H30@3166.93,4217.43 ccw(c3144.73,4239.63) 3176.12,4239.63 ccw(c3207.5,4239.61) PROTOTYPE1.H30@3185.31,4217.43 ; PROTOTYPE1.H30@3176.12,4208.23 3176.12,4316.31 3193.19,4333.37 3723.52,4333.37 3734.19,4322.71 3781.86,4322.71 3792.52,4333.37 v1(3873.52,4333.37) ; 3176.12,4278.24 ccw(c3246.13,4278.24) PROTOTYPE1.H30@3196.63,4228.74 ; v1@3866.81,4326.66 ccw(c3850.59,4310.44) 3850.59,4333.37 ccw(c3850.59,4356.31) v1@3866.81,4340.09 ; v1@3869.64,4329.49 ccw(c3860.25,4320.1) 3860.25,4333.37 ccw(c3860.25,4346.65) v1@3869.64,4337.26
ATE.UIO.IO32: J33.B36 PROTOTYPE1.H31 U8.P9 UH2.16 | length 10071.3
  Top Layer w4: UH2.16@3073.76,4813.23 3109.4,4777.59 ; UH2.16@3077.91,4794.15 cw(c3082.8,4771.7) 3099.04,4787.95 cw(c3115.29,4804.2) UH2.16@3092.84,4809.08 ; UH2.16@3078.76,4790.24 cw(c3084.65,4763.19) 3104.22,4782.77 cw(c3123.8,4802.34) UH2.16@3096.75,4808.23 ; UH2.16@3079.61,4786.34 cw(c3086.5,4754.69) 3109.4,4777.59 ; UH2.16@3100.66,4807.38 ccw(c3132.31,4800.49) 3109.4,4777.59 ; PROTOTYPE1.H31@3255.62,4228.74 ccw(c3206.11,4278.25) 3276.12,4278.25 ccw(c3346.13,4278.25) PROTOTYPE1.H31@3296.63,4228.74 ; PROTOTYPE1.H31@3258.44,4225.91 ccw(c3215.77,4268.59) 3276.12,4268.59 ccw(c3336.48,4268.59) PROTOTYPE1.H31@3293.8,4225.91 ; PROTOTYPE1.H31@3261.27,4223.08 ccw(c3225.42,4258.93) 3276.12,4258.93 ccw(c3326.82,4258.93) PROTOTYPE1.H31@3290.97,4223.08 ; v1@3264.02,4308.37 ccw(c3241.09,4308.37) 3257.31,4324.59 ccw(c3273.52,4340.81) v1@3273.52,4317.87 ; PROTOTYPE1.H31@3264.1,4220.26 ccw(c3235.08,4249.28) 3276.12,4249.28 ccw(c3317.16,4249.28) PROTOTYPE1.H31@3288.14,4220.26 ; v1@3266.81,4301.66 cw(c3244.32,4279.17) 3276.12,4279.17 ; PROTOTYPE1.H31@3266.93,4217.43 ccw(c3244.74,4239.62) 3276.12,4239.62 ccw(c3307.51,4239.62) PROTOTYPE1.H31@3285.31,4217.43 ; v1@3268.02,4308.37 ccw(c3254.75,4308.37) 3264.14,4317.76 ccw(c3273.52,4327.15) v1@3273.52,4313.87 ; v1@3269.64,4304.49 cw(c3253.98,4288.83) 3276.12,4288.83 ; PROTOTYPE1.H31@3276.12,4208.23 3276.12,4305.78 v1(3273.52,4308.37) 3109.4,4472.49 3109.4,4777.59 ; 3276.12,4291.71 cw(c3290.19,4291.71) v1@3280.24,4301.66 ; v3(5193.15,4150.63) U8.P9@5212.83,4170.31 ; U8.P9@5205.33,4170.31 cw(c5187.23,4170.31) 5200.03,4157.51 cw(c5212.83,4144.71) U8.P9@5212.83,4162.81 ; U8.P9@5205.49,4170.31 cw(c5187.77,4170.31) 5200.3,4157.78 cw(c5212.83,4145.25) U8.P9@5212.83,4162.97 ; 5205.95,4163.43 cw(c5193.15,4176.24) 5193.15,4158.13 ccw(c5193.15,4176.24) 5205.95,4163.43 ; 5205.95,4163.43 ccw(c5218.76,4150.63) 5200.65,4150.63 cw(c5218.76,4150.63) 5205.95,4163.43
  MidLayer1 w4: v1(2916.19,3150.04) 2923.52,3150.04 3123.52,3350.04 3123.52,4143.52 3140,4160 3227.89,4160 ; v1@2916.19,3151.54 ccw(c2916.19,3172.87) 2931.27,3157.79 ; v1@2916.19,3155.54 ccw(c2916.19,3186.52) 2938.1,3164.62 ; v1@2916.19,3159.54 ccw(c2916.19,3200.18) 2944.93,3171.44 ; v1@2925.69,3150.04 cw(c2930.92,3150.04) 2927.22,3153.74 ; PROTOTYPE1.H31@3247.13,4207.7 cw(c3181.42,4206.47) 3227.89,4160 ; PROTOTYPE1.H31@3251.13,4207.77 cw(c3194.48,4206.72) 3234.54,4166.66 cw(c3274.6,4126.59) PROTOTYPE1.H31@3275.66,4183.24 ; PROTOTYPE1.H31@3255.12,4207.84 cw(c3207.54,4206.96) 3241.19,4173.31 cw(c3274.85,4139.66) PROTOTYPE1.H31@3275.73,4187.24 ; PROTOTYPE1.H31@3259.12,4207.92 cw(c3220.61,4207.2) 3247.85,4179.96 cw(c3275.09,4152.72) PROTOTYPE1.H31@3275.8,4191.24 ; PROTOTYPE1.H31@3275.58,4179.24 ccw(c3274.36,4113.53) 3227.89,4160 ; PROTOTYPE1.H31@3276.12,4208.23 3227.89,4160
  MidLayer2 w4: v1@-476.53,2809.99 ccw(c-492.74,2793.77) -492.74,2816.71 ccw(c-492.74,2839.64) v1@-476.53,2823.43 ; v1@-473.7,2812.82 ccw(c-483.09,2803.43) -483.09,2816.71 ccw(c-483.09,2829.99) v1@-473.7,2820.6 ; v1(-469.81,2816.71) -661.71,2816.71 -670,2825 -670,2907.38 -661.14,2916.24 -661.14,2924.37 -518.81,3066.71 189.61,3066.71 362.31,2894 1219,2894 1231.86,2906.86 1231.86,2950.37 1265.19,2983.71 1265.19,3032.04 1358.19,3125.04 2197.92,3125.04 2214.25,3141.37 2628.63,3141.37 2636.96,3133.04 2899.19,3133.04 v1(2916.19,3150.04) ; v1@2906.69,3150.04 cw(c2883.76,3150.04) 2899.97,3133.82 cw(c2916.19,3117.61) v1@2916.19,3140.54 ; v1@2910.69,3150.04 cw(c2897.41,3150.04) 2906.8,3140.65 cw(c2916.19,3131.26) v1@2916.19,3144.54
  Bottom Layer w4: J33.B36@-785.98,2810.34 -545,2810.34 -538.63,2816.71 v1(-469.81,2816.71) ; J33.B36@-711.58,2804.84 cw(c-698.3,2791.56) -698.3,2810.34 cw(c-698.3,2829.12) J33.B36@-711.58,2815.84 ; J33.B36@-708.76,2802.01 cw(c-688.65,2781.9) -688.65,2810.34 cw(c-688.64,2838.78) J33.B36@-708.76,2818.67 ; v1@-476.53,2809.99 ccw(c-492.74,2793.77) -492.74,2816.71 ccw(c-492.74,2839.64) v1@-476.53,2823.43 ; v1@-473.7,2812.82 ccw(c-483.09,2803.43) -483.09,2816.71 ccw(c-483.09,2829.99) v1@-473.7,2820.6 ; v1(3273.52,4308.37) 3341.19,4376.04 3361.04,4376.04 4041.6,4376.04 4250.93,4166.71 4419.65,4166.71 4444.65,4141.71 4481.86,4141.71 4498.52,4158.37 4548.52,4158.37 4586.9,4120 4770.15,4120 4785.27,4135.12 4855.26,4135.12 4860,4135.12 4870,4135.12 5076.1,4135.12 5169.64,4135.12 ccw(c5169.64,4149.17) 5179.57,4139.24 ; v1@3273.52,4313.87 ccw(c3273.52,4327.15) 3282.91,4317.76 ccw(c3292.3,4308.37) v1@3279.02,4308.37 ; v1@3273.52,4317.87 ccw(c3273.52,4340.81) 3289.74,4324.59 ccw(c3305.96,4308.37) v1@3283.02,4308.37 ; v3@5185.68,4151.28 cw(c5167.64,4152.86) 5179.28,4138.99 cw(c5190.92,4125.12) v3@5192.5,4143.16
ATE.UIO.IO33: J33.A36 PROTOTYPE1.H32 U8.P4 UH2.17 | length 10171.6
  Top Layer w4: J33.A36@-785.98,2810.34 -527.49,2810.34 -484.14,2853.69 -484.14,3150.71 -235.05,3399.8 -217.35,3417.5 -217.35,3575.02 -100.05,3692.32 -94,3698.37 -94,3821.31 -9.14,3906.17 -9.14,4023.02 -43.14,4057.02 -43.14,4078.17 -13,4108.31 -13,4408 -25,4420 -25,4439.75 18.63,4483.37 228.86,4483.37 270.52,4525.04 v1(270.52,4650.04) ; J33.A36@-711.58,2804.84 cw(c-698.3,2791.56) -698.3,2810.34 cw(c-698.3,2829.12) J33.A36@-711.58,2815.84 ; J33.A36@-708.76,2802.01 cw(c-688.65,2781.9) -688.65,2810.34 cw(c-688.64,2838.78) J33.A36@-708.76,2818.67 ; v1@263.81,4643.32 cw(c247.59,4627.11) 270.52,4627.11 cw(c293.46,4627.11) v1@277.24,4643.32 ; v1@266.64,4646.15 cw(c257.25,4636.76) 270.52,4636.76 cw(c283.8,4636.76) v1@274.41,4646.15 ; UH2.17@3146.33,4715.55 ccw(c3096.5,4719.77) 3131.86,4755.13 ; UH2.17@3150.31,4715.22 ccw(c3107.72,4718.82) 3137.95,4749.04 ccw(c3168.17,4779.27) UH2.17@3171.77,4736.68 ; UH2.17@3154.3,4714.88 ccw(c3118.95,4717.87) 3144.04,4742.96 ccw(c3169.12,4768.04) UH2.17@3172.11,4732.69 ; UH2.17@3158.29,4714.54 ccw(c3130.18,4716.92) 3150.12,4736.87 ccw(c3170.07,4756.81) UH2.17@3172.45,4728.71 ; UH2.17@3171.44,4740.66 cw(c3167.22,4790.5) 3131.86,4755.13 ; UH2.17@3173.76,4713.23 3131.86,4755.13 ; PROTOTYPE1.H32@3355.62,4228.74 ccw(c3312.38,4271.98) 3373.52,4271.98 ; PROTOTYPE1.H32@3358.44,4225.91 ccw(c3322.04,4262.32) 3373.52,4262.32 ; PROTOTYPE1.H32@3361.27,4223.08 ccw(c3331.69,4252.66) 3373.52,4252.66 ; PROTOTYPE1.H32@3364.1,4220.26 ccw(c3341.35,4243.01) 3373.52,4243.01 ; v1@3366.81,4418.32 cw(c3350.59,4402.11) 3373.52,4402.11 cw(c3396.46,4402.11) v1@3380.24,4418.32 ; v1@3366.81,4431.76 ccw(c3350.59,4447.98) 3373.52,4447.98 ccw(c3396.46,4447.98) v1@3380.24,4431.76 ; v1@3369.64,4421.15 cw(c3360.25,4411.76) 3373.52,4411.76 cw(c3386.8,4411.76) v1@3377.41,4421.15 ; v1@3369.64,4428.93 ccw(c3360.25,4438.32) 3373.52,4438.32 ccw(c3386.8,4438.32) v1@3377.41,4428.93 ; 3373.52,4245.89 ccw(c3413.78,4245.89) PROTOTYPE1.H32@3385.31,4217.43 ; 3373.52,4255.55 ccw(c3423.43,4255.55) PROTOTYPE1.H32@3388.14,4220.26 ; 3373.52,4265.2 ccw(c3433.09,4265.2) PROTOTYPE1.H32@3390.97,4223.08 ; 3373.52,4274.86 ccw(c3442.75,4274.86) PROTOTYPE1.H32@3393.8,4225.91 ; 3373.52,4284.52 ccw(c3452.4,4284.52) PROTOTYPE1.H32@3396.63,4228.74 ; PROTOTYPE1.H32@3376.12,4208.23 3373.52,4210.83 v1(3373.52,4425.04) 3373.52,4766.71 3290.19,4850.04 3148.52,4850.04 3131.86,4833.37 3131.86,4755.13 ; v3(4996.3,4150.63) U8.P4@5015.98,4170.31 ; U8.P4@5008.48,4170.31 cw(c4990.38,4170.31) 5003.18,4157.51 cw(c5015.98,4144.71) U8.P4@5015.98,4162.81 ; U8.P4@5008.64,4170.31 cw(c4990.92,4170.31) 5003.45,4157.78 cw(c5015.98,4145.25) U8.P4@5015.98,4162.97 ; 5009.1,4163.43 cw(c4996.3,4176.24) 4996.3,4158.13 ccw(c4996.3,4176.24) 5009.1,4163.43 ; 5009.1,4163.43 ccw(c5021.91,4150.63) 5003.8,4150.63 cw(c5021.91,4150.63) 5009.1,4163.43
  MidLayer1 w4: v1@4699.34,4217.83 cw(c4687.8,4204.38) 4705.52,4204.38 ; v1@4701.94,4220.87 cw(c4695.26,4213.08) 4705.52,4213.08 cw(c4715.79,4213.08) v1@4709.11,4220.87 ; v1(4705.52,4225.04) 4705.52,4204.37 ; v1@4711.71,4217.83 ccw(c4723.25,4204.38) 4705.52,4204.38 ; v3@4991.11,4145.44 ccw(c4978.57,4132.9) 4978.57,4150.63 ccw(c4978.57,4168.36) v3@4991.11,4155.82 ; v3(4996.3,4150.63) 4918.62,4150.63 4870,4150.63 4860,4150.63 4793.87,4150.63 4770.79,4173.71 4736.19,4173.71 4705.52,4204.37 ; 4978.19,4150.63 cw(c4978.19,4132.52) 4991,4145.33 ccw(c4978.19,4132.52) 4978.19,4150.63 ; 4978.19,4150.63 ccw(c4978.19,4168.74) 4991,4155.93 cw(c4978.19,4168.74) 4978.19,4150.63
  MidLayer2 w4: v1(270.52,4650.04) 293.96,4650.04 295,4649 463.25,4649 476.44,4635.81 974.07,4635.81 1010.17,4599.71 1634.71,4599.71 1651.71,4616.71 2481.86,4616.71 2523.52,4658.37 2523.52,4743.52 2540,4760 3126.99,4760 UH2.17@3173.76,4713.23 ; v1@274.41,4646.15 cw(c283.8,4636.76) 283.8,4650.04 cw(c283.8,4663.32) v1@274.41,4653.93 ; v1@277.24,4643.32 cw(c293.46,4627.11) 293.46,4650.04 cw(c293.46,4672.98) v1@277.24,4656.76 ; UH2.17@3146.23,4713.33 ccw(c3080.56,4713.56) 3127,4760 ccw(c3173.44,4806.44) UH2.17@3173.66,4740.76 ; UH2.17@3150.23,4713.32 ccw(c3094.1,4713.51) 3133.79,4753.2 ccw(c3173.48,4792.9) UH2.17@3173.68,4736.76 ; UH2.17@3154.23,4713.3 ccw(c3107.64,4713.46) 3140.59,4746.41 ccw(c3173.53,4779.35) UH2.17@3173.69,4732.76 ; UH2.17@3158.23,4713.29 ccw(c3121.19,4713.42) 3147.38,4739.61 ccw(c3173.58,4765.81) UH2.17@3173.71,4728.76
  Bottom Layer w4: v1@3373.52,4415.54 cw(c3373.52,4392.61) 3389.74,4408.82 cw(c3405.96,4425.04) v1@3383.02,4425.04 ; v1@3373.52,4419.54 cw(c3373.52,4406.26) 3382.91,4415.65 cw(c3392.3,4425.04) v1@3379.02,4425.04 ; v1(3373.52,4425.04) 3390.52,4408.04 4054.86,4408.04 4083.58,4379.32 4212.86,4250.04 4412.21,4250.04 4420.54,4258.37 4478.86,4258.37 4572.73,4164.5 4667.4,4164.5 4681.86,4150.04 4710.04,4150.04 4723.52,4163.52 4723.52,4185.04 4705.52,4203.04 ; v1@4699.01,4218.13 cw(c4684.8,4203.04) 4705.52,4203.04 ; v1@4701.75,4221.04 cw(c4693.53,4212.3) 4705.52,4212.3 cw(c4717.52,4212.3) v1@4709.3,4221.04 ; v1(4705.52,4225.04) 4705.52,4203.04 ; v1@4712.04,4218.13 ccw(c4726.25,4203.04) 4705.52,4203.04
ATE.UIO.IO34: J33.A37 PROTOTYPE1.A32 U8.R4 UH2.18 | length 10163.2
  Top Layer w4: J33.A37@-781.91,2775.04 -551.48,2775.04 -493.14,2833.37 -476.14,2850.35 -476.14,3147.39 -209.35,3414.19 -209.35,3571.71 -86,3695.06 -86,3818 -1.14,3902.86 -1.14,4026.33 -34.81,4060 -34.81,4075.19 -5,4105 v1(-5,4435) ; J33.A37@-714.41,2768.3 cw(c-698.14,2752.02) -698.14,2775.04 ; J33.A37@-711.58,2765.47 cw(c-688.48,2742.37) -688.48,2775.04 ; J33.A37@-708.76,2762.64 cw(c-678.82,2732.71) -678.82,2775.04 ; J33.A37@-708.76,2779.3 ccw(c-698.47,2789.58) -698.47,2775.04 ; v1@-11.72,4428.28 cw(c-27.94,4412.06) -5,4412.06 cw(c17.93,4412.06) v1@1.72,4428.28 ; v1@-8.89,4431.11 cw(c-18.28,4421.72) -5,4421.72 cw(c8.28,4421.72) v1@-1.11,4431.11 ; UH2.18@3173.76,4785.71 cw(c3173.76,4719.25) 3220.75,4766.24 cw(c3267.74,4813.23) UH2.18@3201.29,4813.23 ; UH2.18@3173.76,4789.71 cw(c3173.76,4732.91) 3213.92,4773.07 cw(c3254.09,4813.23) UH2.18@3197.29,4813.23 ; UH2.18@3173.76,4793.71 cw(c3173.76,4746.56) 3207.09,4779.9 cw(c3240.43,4813.23) UH2.18@3193.29,4813.23 ; UH2.18@3173.76,4797.71 cw(c3173.76,4760.22) 3200.27,4786.73 cw(c3226.77,4813.23) UH2.18@3189.29,4813.23 ; UH2.18@3173.76,4813.23 3226.07,4760.92 3305,4760.92 3331.86,4734.06 3331.86,4198.71 3376.12,4154.44 ; PROTOTYPE1.A32@3363.51,4134.35 ccw(c3353.81,4154.44) 3376.12,4154.44 ; PROTOTYPE1.A32@3365.25,4130.75 ccw(c3356.89,4148.07) 3376.12,4148.07 ccw(c3395.36,4148.07) PROTOTYPE1.A32@3386.99,4130.75 ; PROTOTYPE1.A32@3366.99,4127.15 ccw(c3359.96,4141.7) 3376.12,4141.7 ccw(c3392.28,4141.7) PROTOTYPE1.A32@3385.25,4127.15 ; PROTOTYPE1.A32@3376.12,4108.23 3376.12,4154.44 ; PROTOTYPE1.A32@3388.73,4134.35 cw(c3398.43,4154.44) 3376.12,4154.44 ; v3(4996.3,4111.26) U8.R4@5015.98,4130.94 ; U8.R4@5008.48,4130.94 cw(c4990.38,4130.94) 5003.18,4118.14 cw(c5015.98,4105.34) U8.R4@5015.98,4123.44 ; U8.R4@5008.64,4130.94 cw(c4990.92,4130.94) 5003.45,4118.41 cw(c5015.98,4105.88) U8.R4@5015.98,4123.6 ; 5009.1,4124.06 cw(c4996.3,4136.87) 4996.3,4118.76 ccw(c4996.3,4136.87) 5009.1,4124.06 ; 5009.1,4124.06 ccw(c5021.91,4111.26) 5003.8,4111.26 cw(c5021.91,4111.26) 5009.1,4124.06
  MidLayer1 w4: v1@4190,4075 4273.82,4075 4330.52,4131.71 4480.19,4131.71 4506.86,4158.37 4556.86,4158.37 4565.19,4150.04 4565.19,4140.04 4581.52,4123.71 4636.78,4123.71 4640.78,4119.71 4692.46,4119.71 4700.66,4127.92 4741.93,4127.92 4749.31,4120.54 4761.95,4120.54 4765.78,4116.71 4800,4116.71 4818.78,4116.71 4824.23,4111.26 4860,4111.26 4870,4111.26 4918.62,4111.26 v3(4996.3,4111.26) ; v1@4194.08,4071.15 cw(c4203.37,4061.86) 4203.37,4075 ; v1@4194.08,4078.93 ccw(c4203.57,4088.42) 4203.57,4075 ; v1@4196.91,4068.32 cw(c4213.03,4052.2) 4213.03,4075 ; v1@4196.91,4081.76 ccw(c4213.22,4098.07) 4213.22,4075 ; v3@4991,4105.96 ccw(c4978.19,4093.15) 4978.19,4111.26 ccw(c4978.19,4129.37) v3@4991,4116.56 ; v3@4991.11,4106.07 ccw(c4978.57,4093.53) 4978.57,4111.26 ccw(c4978.57,4128.99) v3@4991.11,4116.45
  MidLayer2 w4: v1@-5,4428.5 ccw(c-5,4445.36) 6.92,4433.44 ; v1@-5,4432.5 ccw(c-5,4459.01) 13.75,4440.27 ; v1(-5,4435) 8.48,4435 40.52,4467.04 401.26,4467.04 522.03,4587.81 850.88,4587.81 882.19,4556.5 1452.61,4556.5 1463.49,4567.37 1498.88,4567.37 1526.25,4540 3200.19,4540 3215.19,4555 3215.19,4771.8 ; v1@-5,4436.5 ccw(c-5,4472.67) 20.58,4447.09 ; v1@-5,4440.5 ccw(c-5,4486.33) 27.41,4453.92 ; v1@-5,4444.5 ccw(c-5,4499.98) 34.23,4460.75 ; UH2.18@3173.76,4813.23 3215.19,4771.8 ; UH2.18@3175.2,4797.77 cw(c3177.75,4770.48) 3197.13,4789.86 cw(c3216.51,4809.25) UH2.18@3189.22,4811.79 ; UH2.18@3175.57,4793.79 cw(c3178.78,4759.47) 3203.15,4783.84 cw(c3227.52,4808.22) UH2.18@3193.2,4811.42 ; UH2.18@3175.94,4789.81 cw(c3179.8,4748.46) 3209.17,4777.82 cw(c3238.53,4807.19) UH2.18@3197.18,4811.05 ; UH2.18@3176.32,4785.83 cw(c3180.83,4737.45) 3215.19,4771.8 ; UH2.18@3201.17,4810.68 ccw(c3249.55,4806.16) 3215.19,4771.8
  Bottom Layer w4: PROTOTYPE1.A32@3376.12,4108.23 3376.12,4108.37 3506.86,4108.37 3523.52,4091.71 3523.52,3991.71 3548.52,3966.71 3648.52,3966.71 3723.52,4041.71 3940.19,4041.71 3965.19,4016.71 3990.19,4016.71 4006.86,4033.37 4148.52,4033.37 v1(4190.19,4075.04) ; PROTOTYPE1.A32@3385.31,4099.04 cw(c3407.84,4076.51) 3407.84,4108.37 ; PROTOTYPE1.A32@3385.31,4117.43 ccw(c3407.17,4139.28) 3407.17,4108.37 ; PROTOTYPE1.A32@3388.14,4096.21 cw(c3417.5,4066.85) 3417.5,4108.37 ; PROTOTYPE1.A32@3388.14,4120.26 ccw(c3416.82,4148.94) 3416.82,4108.37 ; PROTOTYPE1.A32@3390.97,4093.39 cw(c3427.16,4057.2) 3427.16,4108.37 ; PROTOTYPE1.A32@3390.97,4123.08 ccw(c3426.48,4158.59) 3426.48,4108.37 ; PROTOTYPE1.A32@3393.8,4090.56 cw(c3436.81,4047.54) 3436.81,4108.37 ; PROTOTYPE1.A32@3393.8,4125.91 ccw(c3436.14,4168.25) 3436.14,4108.37 ; PROTOTYPE1.A32@3396.63,4087.73 cw(c3446.47,4037.88) 3446.47,4108.37 ; PROTOTYPE1.A32@3396.63,4128.74 ccw(c3445.8,4177.91) 3445.8,4108.37 ; v1@4180.69,4075.04 cw(c4157.76,4075.04) 4173.97,4058.82 cw(c4190.19,4042.61) v1@4190.19,4065.54 ; v1@4184.69,4075.04 cw(c4171.41,4075.04) 4180.8,4065.65 cw(c4190.19,4056.26) v1@4190.19,4069.54
ATE.UIO.IO35: J33.B37 PROTOTYPE1.B32 U8.R10 UH2.19 | length 10295.6
  Top Layer w4: UH2.19@3273.76,4713.23 3320,4666.99 3320,4064.36 PROTOTYPE1.B32@3376.12,4008.23 ; UH2.19@3273.94,4697.71 cw(c3274.35,4661.66) 3299.84,4687.15 cw(c3325.33,4712.64) UH2.19@3289.29,4713.06 ; UH2.19@3273.98,4693.71 cw(c3274.5,4648.38) 3306.56,4680.43 cw(c3338.61,4712.49) UH2.19@3293.28,4713.01 ; UH2.19@3274.03,4689.71 cw(c3274.66,4635.09) 3313.28,4673.71 cw(c3351.9,4712.34) UH2.19@3297.28,4712.96 ; UH2.19@3274.08,4685.71 cw(c3274.81,4621.81) 3320,4667 cw(c3365.18,4712.18) UH2.19@3301.28,4712.92 ; PROTOTYPE1.B32@3347.12,4008.23 ccw(c3277.11,4008.23) 3326.62,4057.74 ccw(c3376.12,4107.25) PROTOTYPE1.B32@3376.12,4037.23 ; PROTOTYPE1.B32@3351.12,4008.23 ccw(c3290.77,4008.23) 3333.44,4050.91 ccw(c3376.12,4093.59) PROTOTYPE1.B32@3376.12,4033.23 ; PROTOTYPE1.B32@3355.12,4008.23 ccw(c3304.42,4008.23) 3340.27,4044.08 ccw(c3376.12,4079.93) PROTOTYPE1.B32@3376.12,4029.23 ; PROTOTYPE1.B32@3359.12,4008.23 ccw(c3318.08,4008.23) 3347.1,4037.26 ccw(c3376.12,4066.28) PROTOTYPE1.B32@3376.12,4025.23 ; PROTOTYPE1.B32@3363.12,4008.23 ccw(c3331.74,4008.23) 3353.93,4030.43 ccw(c3376.12,4052.62) PROTOTYPE1.B32@3376.12,4021.23 ; v3(5232.52,4111.26) U8.R10@5252.2,4130.94 ; U8.R10@5244.7,4130.94 cw(c5226.6,4130.94) 5239.4,4118.14 cw(c5252.2,4105.34) U8.R10@5252.2,4123.44 ; U8.R10@5244.86,4130.94 cw(c5227.14,4130.94) 5239.67,4118.41 cw(c5252.2,4105.88) U8.R10@5252.2,4123.6 ; 5245.32,4124.06 cw(c5232.52,4136.87) 5232.52,4118.76 ccw(c5232.52,4136.87) 5245.32,4124.06 ; 5245.32,4124.06 ccw(c5258.13,4111.26) 5240.02,4111.26 cw(c5258.13,4111.26) 5245.32,4124.06
  MidLayer1 w4: v1(2695,2725) 2809.19,2725 3331.86,3247.67 3331.86,3963.97 ; v1@2698.89,2721.11 cw(c2708.28,2711.72) 2708.28,2725 cw(c2708.28,2738.28) v1@2698.89,2728.89 ; v1@2701.72,2718.28 cw(c2717.93,2702.06) 2717.93,2725 cw(c2717.93,2747.93) v1@2701.72,2731.72 ; PROTOTYPE1.B32@3347.22,4005.85 cw(c3294.34,4001.49) 3331.86,3963.97 ; PROTOTYPE1.B32@3351.21,4006.18 cw(c3305.62,4002.42) 3337.96,3970.08 cw(c3370.31,3937.74) PROTOTYPE1.B32@3374.07,3983.32 ; PROTOTYPE1.B32@3355.19,4006.51 cw(c3316.9,4003.35) 3344.07,3976.18 cw(c3371.24,3949.02) PROTOTYPE1.B32@3374.39,3987.31 ; PROTOTYPE1.B32@3359.18,4006.84 cw(c3328.18,4004.28) 3350.17,3982.29 cw(c3372.17,3960.3) PROTOTYPE1.B32@3374.72,3991.29 ; PROTOTYPE1.B32@3373.74,3979.33 ccw(c3369.37,3926.46) 3331.86,3963.97 ; PROTOTYPE1.B32@3376.12,4008.23 3331.86,3963.97
  MidLayer2 w4: v1(490.19,3000.04) 631.86,3000.04 v1(699.19,2932.71) ; v1@494.08,2996.15 cw(c503.47,2986.76) 503.47,3000.04 cw(c503.47,3013.32) v1@494.08,3003.93 ; v1@496.91,2993.32 cw(c513.13,2977.11) 513.13,3000.04 cw(c513.13,3022.98) v1@496.91,3006.76 ; v1@689.69,2932.71 ccw(c666.76,2932.71) 682.97,2948.93 ccw(c699.19,2965.14) v1@699.19,2942.21 ; v1@693.69,2932.71 ccw(c680.41,2932.71) 689.8,2942.1 ccw(c699.19,2951.49) v1@699.19,2938.21 ; PROTOTYPE1.B32@3347.54,4013.15 ccw(c3308.55,4019.86) 3336.53,4047.83 ; PROTOTYPE1.B32@3351.48,4012.47 ccw(c3317.87,4018.25) 3341.99,4042.37 ccw(c3366.1,4066.48) PROTOTYPE1.B32@3371.88,4032.87 ; PROTOTYPE1.B32@3355.43,4011.79 ccw(c3327.19,4016.65) 3347.45,4036.91 ccw(c3367.71,4057.16) PROTOTYPE1.B32@3372.56,4028.93 ; PROTOTYPE1.B32@3359.37,4011.12 ccw(c3336.51,4015.05) 3352.91,4031.45 ccw(c3369.31,4047.84) PROTOTYPE1.B32@3373.24,4024.99 ; PROTOTYPE1.B32@3371.21,4036.82 cw(c3364.5,4075.8) 3336.53,4047.83 ; PROTOTYPE1.B32@3376.12,4008.23 3336.52,4047.83 ; v1@3689.02,4175.04 cw(c3666.09,4175.04) 3682.31,4158.82 cw(c3698.52,4142.61) v1@3698.52,4165.54 ; v1@3693.02,4175.04 cw(c3679.75,4175.04) 3689.13,4165.65 cw(c3698.52,4156.26) v1@3698.52,4169.54 ; v1(3698.52,4175.04) 3681.86,4158.37 3372.19,4158.37 3336.52,4122.71 3336.52,4047.83
  Bottom Layer w4: J33.B37@-785.98,2770.97 -480.55,2770.97 -451.48,2800.04 -451.48,3033.37 -434.81,3050.04 440.19,3050.04 v1(490.19,3000.04) ; J33.B37@-711.58,2765.47 cw(c-698.3,2752.19) -698.3,2770.97 cw(c-698.3,2789.75) J33.B37@-711.58,2776.47 ; J33.B37@-708.76,2762.64 cw(c-688.65,2742.53) -688.65,2770.97 cw(c-688.65,2799.41) J33.B37@-708.76,2779.3 ; v1@480.69,3000.04 ccw(c457.76,3000.04) 473.97,3016.26 ccw(c490.19,3032.48) v1@490.19,3009.54 ; v1@484.69,3000.04 ccw(c471.41,3000.04) 480.8,3009.43 ccw(c490.19,3018.82) v1@490.19,3005.54 ; v1@699.19,2923.21 cw(c699.19,2900.27) 715.41,2916.49 cw(c731.63,2932.71) v1@708.69,2932.71 ; v1@699.19,2927.21 cw(c699.19,2913.93) 708.58,2923.32 cw(c717.97,2932.71) v1@704.69,2932.71 ; v1(699.19,2932.71) 748.52,2883.37 1484.96,2883.37 1498.46,2869.87 1528.69,2869.87 1690.52,2708.04 2678.04,2708.04 v1(2695,2725) ; v1@2685.5,2725 cw(c2662.56,2725) 2678.78,2708.78 cw(c2695,2692.56) v1@2695,2715.5 ; v1@2689.5,2725 cw(c2676.22,2725) 2685.61,2715.61 cw(c2695,2706.22) v1@2695,2719.5 ; v1@3698.52,4165.54 cw(c3698.52,4142.61) 3714.74,4158.82 cw(c3730.96,4175.04) v1@3708.02,4175.04 ; v1@3698.52,4169.54 cw(c3698.52,4156.26) 3707.91,4165.65 cw(c3717.3,4175.04) v1@3704.02,4175.04 ; v1(3698.52,4175.04) 3765.52,4108.04 4106.33,4108.04 4108.29,4110 4195,4110 4221.96,4083.04 4522.13,4083.04 4535,4095.92 4728.67,4095.92 4737.19,4087.4 4855.26,4087.4 4860,4087.4 4870,4087.4 5076.1,4087.4 5095.52,4087.4 5169.64,4087.4 5189.14,4087.4 ccw(c5189.14,4129.13) 5218.65,4099.62 ; v3@5225.05,4111.91 cw(c5207.01,4113.49) 5218.65,4099.62 ; v3@5231.87,4103.79 ccw(c5230.29,4085.75) 5218.65,4099.62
